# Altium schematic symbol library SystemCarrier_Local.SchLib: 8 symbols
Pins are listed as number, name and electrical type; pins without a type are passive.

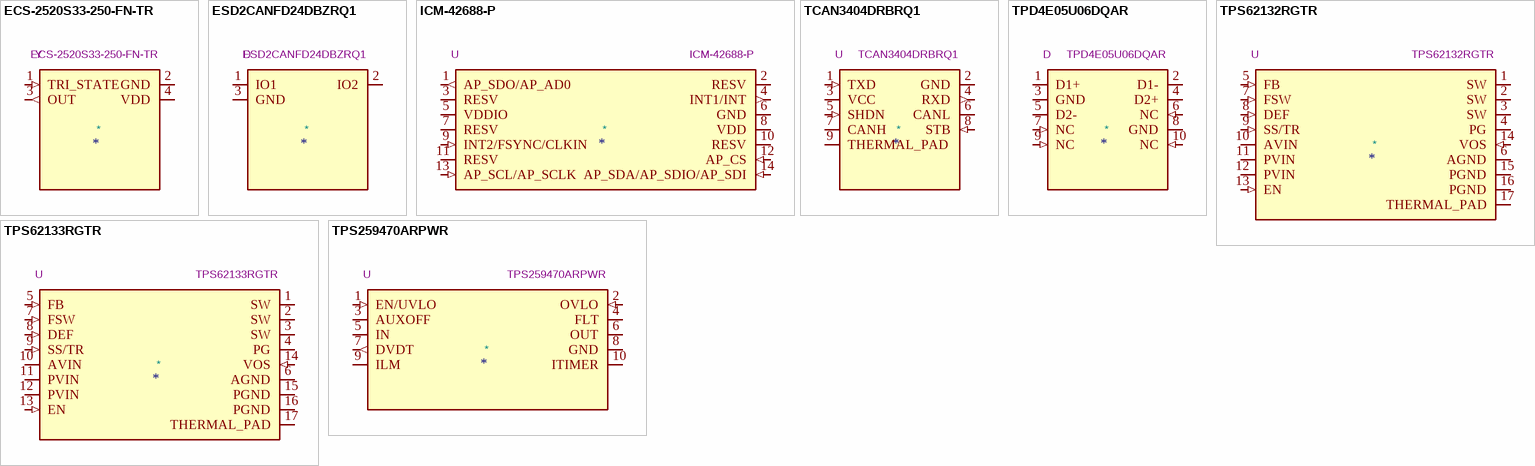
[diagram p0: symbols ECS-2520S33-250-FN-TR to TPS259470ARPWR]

## ECS-2520S33-250-FN-TR
designator *  value ECS-2520S33-250-FN-TR  Reference: Y
Generated from SYMBOL_PIN_CONTRACT_SYS_001.csv for ECS-2520S33-250-FN-TR
pins: 1 TRI_STATE (in), 2 GND (power), 3 OUT (out), 4 VDD (power)

## ESD2CANFD24DBZRQ1
designator *  value ESD2CANFD24DBZRQ1  Reference: D
Generated from SYMBOL_PIN_CONTRACT_SYS_001.csv for ESD2CANFD24DBZRQ1
pins: 1 IO1 (io), 2 IO2 (io), 3 GND

## ICM-42688-P
designator *  value ICM-42688-P  Reference: U
Generated from SYMBOL_PIN_CONTRACT_SYS_001.csv for ICM-42688-P
pins: 1 AP_SDO/AP_AD0 (out), 2 RESV, 3 RESV, 4 INT1/INT (out), 5 VDDIO (power), 6 GND (power), 7 RESV, 8 VDD (power), 9 INT2/FSYNC/CLKIN (in), 10 RESV, 11 RESV, 12 AP_CS (in), 13 AP_SCL/AP_SCLK (in), 14 AP_SDA/AP_SDIO/AP_SDI (in)

## TCAN3404DRBRQ1
designator *  value TCAN3404DRBRQ1  Reference: U
Generated from SYMBOL_PIN_CONTRACT_SYS_001.csv for TCAN3404DRBRQ1
pins: 1 TXD (in), 2 GND (power), 3 VCC (power), 4 RXD (out), 5 SHDN (in), 6 CANL (io), 7 CANH (io), 8 STB (in), 9 THERMAL_PAD (power)

## TPD4E05U06DQAR
designator *  value TPD4E05U06DQAR  Reference: D
Generated from SYMBOL_PIN_CONTRACT_SYS_001.csv for TPD4E05U06DQAR
pins: 1 D1+ (io), 2 D1- (io), 3 GND, 4 D2+ (io), 5 D2- (io), 6 NC (in), 7 NC (in), 8 GND, 9 NC (in), 10 NC (in)

## TPS62132RGTR
designator *  value TPS62132RGTR  Reference: U
Generated from SYMBOL_PIN_CONTRACT_SYS_001.csv for TPS62132RGTR
pins: 1 SW, 2 SW, 3 SW, 4 PG (oc), 5 FB (in), 6 AGND (power), 7 FSW (in), 8 DEF (in), 9 SS/TR (in), 10 AVIN (power), 11 PVIN (power), 12 PVIN (power), 13 EN (in), 14 VOS (in), 15 PGND (power), 16 PGND (power), 17 THERMAL_PAD (power)

## TPS62133RGTR
designator *  value TPS62133RGTR  Reference: U
Generated from SYMBOL_PIN_CONTRACT_SYS_001.csv for TPS62133RGTR
pins: 1 SW, 2 SW, 3 SW, 4 PG (oc), 5 FB (in), 6 AGND (power), 7 FSW (in), 8 DEF (in), 9 SS/TR (in), 10 AVIN (power), 11 PVIN (power), 12 PVIN (power), 13 EN (in), 14 VOS (in), 15 PGND (power), 16 PGND (power), 17 THERMAL_PAD (power)

## TPS259470ARPWR
designator *  value TPS259470ARPWR  Reference: U
Generated from SYMBOL_PIN_CONTRACT_SYS_001.csv for TPS259470ARPWR
pins: 1 EN/UVLO (in), 2 OVLO (in), 3 AUXOFF (oc), 4 FLT (oc), 5 IN (power), 6 OUT (power), 7 DVDT (out), 8 GND (power), 9 ILM (io), 10 ITIMER (io)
